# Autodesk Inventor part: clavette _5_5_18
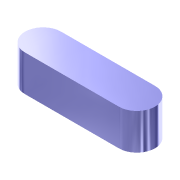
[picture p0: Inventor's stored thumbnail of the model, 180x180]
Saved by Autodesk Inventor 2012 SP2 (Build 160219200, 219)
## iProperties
Created: 2013-04
Part Number: clavette _5_5_18
Material: Default
Document SubType Name: Modeling
Designer: papa
Density: 1 g/cm^3
Mass: 0.423175 g
Surface Area: 3.7781 cm^2
Volume: 0.423175 cm^3
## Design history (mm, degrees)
node "clavette _5_5_181"
node "clavette _5_5_18"
node "Base1"
